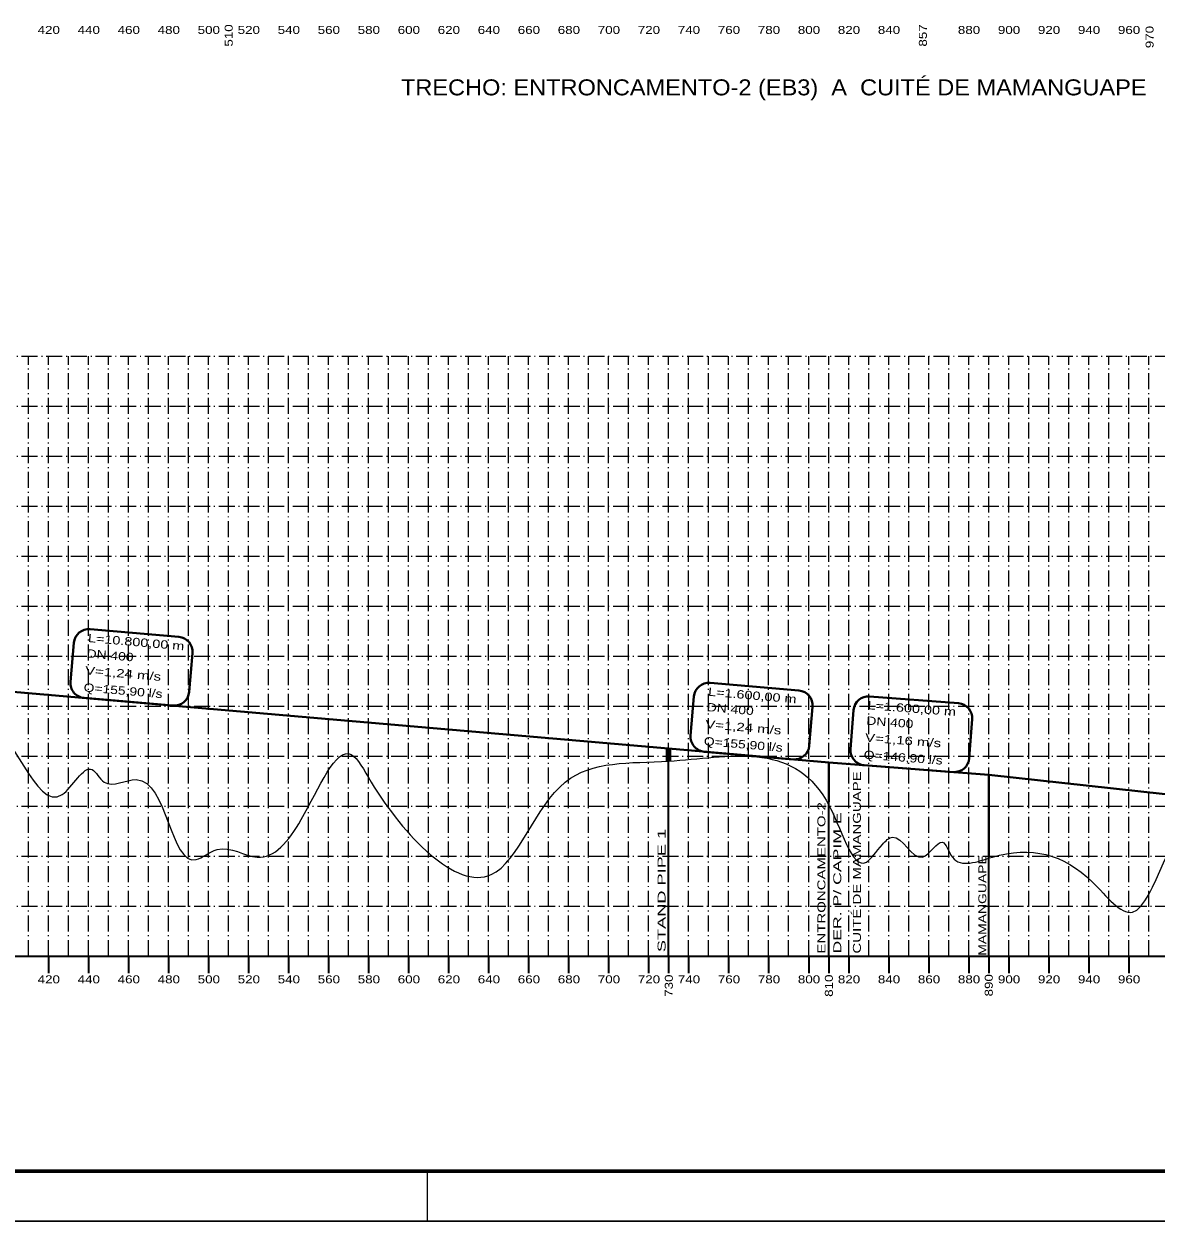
# Model space of a CAD drawing. Extents: x -4 to 42046, y -3 to 29697.
# Drawn here: x 11261 to 22579, y -3 to 11967 of the extents above; entities that cross this region are included whole.
import ezdxf
from ezdxf.enums import TextEntityAlignment as Align

# ---------------------------------------------------------------- set-up
doc = ezdxf.new("R2010")
doc.units = 0
doc.header["$LTSCALE"] = 32
doc.linetypes.add('DOT_DASHED', pattern=[7.7, 5, -1.2, 0.3, -1.2])
for name, color, linetype, lineweight in [('1', 7, 'DOT_DASHED', 13), ('24', 7, 'Continuous', 35), ('56', 7, 'Continuous', 13), ('62', 7, 'Continuous', 13), ('63', 7, 'Continuous', 25), ('7', 7, 'Continuous', 35), ('9', 7, 'Continuous', 40)]:
    doc.layers.add(name, color=color, linetype=linetype, lineweight=lineweight)

msp = doc.modelspace()

# ---------------------------------------------------------------- linework, layer by layer
at = {"layer": '1'}
for p, q in [((3105.77, 8646.17), (29145.77, 8646.17)), ((11305.77, 2646.17), (11305.77, 8646.17)), ((11505.77, 2646.17), (11505.77, 8646.17)), ((11705.77, 2646.17), (11705.77, 8646.17)), ((11905.77, 2646.17), (11905.77, 8646.17)), ((12105.77, 2646.17), (12105.77, 8646.17)), ((12305.77, 2646.17), (12305.77, 8646.17)), ((12505.77, 2646.17), (12505.77, 8646.17)), ((12705.77, 2646.17), (12705.77, 8646.17)), ((12905.77, 2646.17), (12905.77, 8646.17)), ((13105.77, 2646.17), (13105.77, 8646.17)), ((13305.77, 2646.17), (13305.77, 8646.17)), ((13505.77, 2646.17), (13505.77, 8646.17)), ((13705.77, 2646.17), (13705.77, 8646.17)), ((13905.77, 2646.17), (13905.77, 8646.17)), ((14105.77, 2646.17), (14105.77, 8646.17)), ((14305.77, 2646.17), (14305.77, 8646.17)), ((14505.77, 2646.17), (14505.77, 8646.17)), ((14705.77, 2646.17), (14705.77, 8646.17)), ((14905.77, 2646.17), (14905.77, 8646.17)), ((15105.77, 2646.17), (15105.77, 8646.17)), ((15305.77, 2646.17), (15305.77, 8646.17)), ((15505.77, 2646.17), (15505.77, 8646.17)), ((15705.77, 2646.17), (15705.77, 8646.17)), ((15905.77, 2646.17), (15905.77, 8646.17)), ((16105.77, 2646.17), (16105.77, 8646.17)), ((16305.77, 2646.17), (16305.77, 8646.17)), ((16505.77, 2646.17), (16505.77, 8646.17)), ((16705.77, 2646.17), (16705.77, 8646.17)), ((16905.77, 2646.17), (16905.77, 8646.17)), ((17105.77, 2646.17), (17105.77, 8646.17)), ((17305.77, 2646.17), (17305.77, 8646.17)), ((17505.77, 2646.17), (17505.77, 8646.17)), ((17705.77, 2646.17), (17705.77, 8646.17)), ((17905.77, 2646.17), (17905.77, 8646.17)), ((18105.77, 2646.17), (18105.77, 8646.17)), ((18305.77, 2646.17), (18305.77, 8646.17)), ((18505.77, 2646.17), (18505.77, 8646.17)), ((18705.77, 2646.17), (18705.77, 8646.17)), ((18905.77, 2646.17), (18905.77, 8646.17)), ((19105.77, 2646.17), (19105.77, 8646.17)), ((19305.77, 2646.17), (19305.77, 8646.17)), ((19505.77, 2646.17), (19505.77, 8646.17)), ((19705.77, 2646.17), (19705.77, 8646.17)), ((19905.77, 2646.17), (19905.77, 8646.17)), ((20105.77, 2646.17), (20105.77, 8646.17)), ((20305.77, 2646.17), (20305.77, 8646.17)), ((20505.77, 2646.17), (20505.77, 8646.17)), ((20705.77, 2646.17), (20705.77, 8646.17)), ((20905.77, 2646.17), (20905.77, 8646.17)), ((21105.77, 2646.17), (21105.77, 8646.17)), ((21305.77, 2646.17), (21305.77, 8646.17)), ((21505.77, 2646.17), (21505.77, 8646.17)), ((21705.77, 2646.17), (21705.77, 8646.17)), ((21905.77, 2646.17), (21905.77, 8646.17)), ((22105.77, 2646.17), (22105.77, 8646.17)), ((22305.77, 2646.17), (22305.77, 8646.17)), ((22505.77, 2646.17), (22505.77, 8646.17)), ((3105.77, 8146.17), (29145.77, 8146.17)), ((3105.77, 7646.17), (29145.77, 7646.17)), ((3105.77, 7146.17), (29145.77, 7146.17)), ((3105.77, 6646.17), (29145.77, 6646.17)), ((3105.77, 6146.17), (29145.77, 6146.17)), ((3105.77, 5646.17), (29145.77, 5646.17)), ((3105.77, 5146.17), (29145.77, 5146.17)), ((3105.77, 4646.17), (29145.77, 4646.17)), ((3105.77, 4146.17), (29145.77, 4146.17)), ((3105.77, 3646.17), (29145.77, 3646.17)), ((3105.77, 3146.17), (29145.77, 3146.17))]:
    msp.add_line(p, q, dxfattribs=at)
at = {"layer": '56'}
msp.add_spline([(3442.18, 3641.64), (3562.37, 3886.04), (3682.37, 4136.04), (3802.37, 4461.04), (3902.37, 4136.04), (3962.37, 3761.04), (4222.37, 4586.04), (4922.37, 4261.04), (5542.37, 4386.04), (5622.37, 4336.04), (5722.37, 4386.04), (5822.37, 4461.04), (6022.37, 4286.04), (6222.37, 4361.04), (6522.37, 4261.04), (6922.37, 4386.04), (7322.37, 4086.04), (7642.37, 4636.04), (7742.37, 4761.04), (8062.37, 4336.04), (8442.37, 4636.04), (8702.37, 4561.04), (9002.37, 4636.04), (9202.37, 4386.04), (9442.37, 4711.04), (9642.37, 4486.04), (9902.37, 4886.04), (10422.37, 4636.04), (10882.37, 4936.04), (11642.37, 4261.04), (11942.37, 4511.04), (12062.37, 4386.04), (12382.37, 4411.04), (12982.37, 3611.04), (13192.37, 3711.04), (13592.37, 3636.04), (14032.37, 4011.04), (14532.37, 4661.04), (14732.37, 4386.04), (15932.37, 3461.04), (16672.37, 4386.04), (17705.77, 4596.17), (19279.94, 4205.37), (19682.37, 3586.04), (19842.37, 3761.04), (19942.37, 3836.04), (20242.37, 3636.04), (20442.37, 3786.04), (20542.37, 3636.04), (20942.37, 3636.04), (21942.37, 3386.04), (22342.37, 3086.04), (22942.37, 3886.04), (23242.37, 3511.04), (23362.37, 3711.04), (23862.37, 3011.04), (24002.37, 3136.04), (24202.37, 3061.04), (24402.37, 3136.04), (24882.37, 2886.04), (25102.37, 2836.04), (25362.37, 3011.04), (26082.37, 2836.04), (26222.37, 2886.04), (26322.37, 2836.04), (26502.37, 2961.04), (26702.37, 2836.04), (27202.37, 3011.04), (27602.37, 2836.04), (27762.37, 2961.04), (27862.37, 2886.04), (27982.37, 2936.04), (28182.37, 2811.04), (28342.37, 2886.04), (28742.37, 2836.04), (29145.65, 2836.26)], degree=3, dxfattribs=at)
at = {"layer": '62', "lineweight": 35}
for p, q in [((19305.77, 2646.17), (19305.77, 4190.11)), ((20905.77, 2646.17), (20905.77, 3640.84)), ((3105.77, 2646.17), (29145.77, 2646.17)), ((11505.77, 2646.17), (11505.77, 2475.48)), ((11905.77, 2646.17), (11905.77, 2475.48)), ((12305.77, 2646.17), (12305.77, 2475.48)), ((12705.77, 2646.17), (12705.77, 2475.48)), ((13105.77, 2646.17), (13105.77, 2475.48)), ((13505.77, 2646.17), (13505.77, 2475.48)), ((13905.77, 2646.17), (13905.77, 2475.48)), ((14305.77, 2646.17), (14305.77, 2475.48)), ((14705.77, 2646.17), (14705.77, 2475.48)), ((15105.77, 2646.17), (15105.77, 2475.48)), ((15505.77, 2646.17), (15505.77, 2475.48)), ((15905.77, 2646.17), (15905.77, 2475.48)), ((16305.77, 2646.17), (16305.77, 2475.48)), ((16705.77, 2646.17), (16705.77, 2475.48)), ((17105.77, 2646.17), (17105.77, 2475.48)), ((17505.77, 2646.17), (17505.77, 2475.48)), ((17705.77, 2646.17), (17705.77, 2475.48)), ((17905.77, 2646.17), (17905.77, 2475.48)), ((18305.77, 2646.17), (18305.77, 2475.48)), ((18705.77, 2646.17), (18705.77, 2475.48)), ((19105.77, 2646.17), (19105.77, 2475.48)), ((19305.77, 2646.17), (19305.77, 2475.48)), ((19505.77, 2646.17), (19505.77, 2475.48)), ((19905.77, 2646.17), (19905.77, 2475.48)), ((20305.77, 2646.17), (20305.77, 2475.48)), ((20705.77, 2646.17), (20705.77, 2475.48)), ((20905.77, 2646.17), (20905.77, 2475.48)), ((21105.77, 2646.17), (21105.77, 2475.48)), ((21505.77, 2646.17), (21505.77, 2475.48)), ((21905.77, 2646.17), (21905.77, 2475.48)), ((22305.77, 2646.17), (22305.77, 2475.48))]:
    msp.add_line(p, q, dxfattribs=at)
at = {"layer": '63', "lineweight": 60}
msp.add_line((41545.8, 497.03), (1245.8, 497.03), dxfattribs=at)
at = {"layer": '63'}
msp.add_line((15295.8, -2.97), (15295.8, 497.03), dxfattribs=at)
for points in [[(-4.21, -2.97), (42045.8, -2.97), (42045.8, 29697.03)], [(-4.21, -2.97), (42045.8, -2.97), (-4.21, -2.97)]]:
    msp.add_lwpolyline(points, dxfattribs=at)
at = {"layer": '63', "lineweight": 60}
msp.add_lwpolyline([(23554.57, 497.03), (1245.8, 497.03), (1245.8, 29197.03)], dxfattribs=at)
at = {"layer": '7'}
for p, q in [((17688.43, 4596.4), (17688.43, 4715.71)), ((17705.77, 2646.17), (17705.77, 4721.17))]:
    msp.add_line(p, q, dxfattribs=at)
msp.add_lwpolyline([(17723.11, 4595.79), (17723.11, 4715.71), (17688.43, 4715.71)], dxfattribs=at)
at = {"layer": '9'}
for p, q in [((11921.57, 5915), (12809.1, 5838.13)), ((11759.19, 5778.5), (11725.51, 5389.7)), ((12945.59, 5675.74), (12911.92, 5286.94)), ((18121.57, 5378), (19009.1, 5301.13)), ((11862.01, 5227.31), (12749.54, 5150.44)), ((17959.19, 5241.5), (17925.51, 4852.7)), ((19714.79, 5243.33), (20603, 5174.77)), ((19145.59, 5138.74), (19111.92, 4749.94)), ((19553.69, 5105.32), (19523.66, 4716.21)), ((20741.01, 5013.67), (20710.97, 4624.57)), ((18062.01, 4690.31), (18949.54, 4613.44)), ((19305.77, 4190.11), (19305.77, 4582.59)), ((19661.67, 4555.11), (20549.88, 4486.56)), ((20905.77, 3640.84), (20905.77, 4459.09))]:
    msp.add_line(p, q, dxfattribs=at)
msp.add_lwpolyline([(3105.77, 6140.34), (4205.77, 5946.84), (6905.77, 5656.59), (17705.77, 4721.17), (19305.77, 4582.59), (20905.77, 4459.09), (29145.77, 3554.09)], dxfattribs=at)
for centre, start, end in [((11908.63, 5765.56), 85.0498, 175.0498), ((12796.15, 5688.69), 355.0498, 85.0498), ((11874.95, 5376.75), 175.0498, 265.0498), ((12762.48, 5299.88), 265.0498, 355.0498), ((18108.63, 5228.56), 85.0498, 175.0498), ((18996.15, 5151.69), 355.0498, 85.0498), ((19703.24, 5093.77), 85.58623, 175.58623), ((20591.45, 5025.22), 355.58623, 85.58623), ((18074.95, 4839.75), 175.0498, 265.0498), ((18962.48, 4762.88), 265.0498, 355.0498), ((19673.21, 4704.67), 175.58623, 265.58623), ((20561.42, 4636.11), 265.58623, 355.58623)]:
    msp.add_arc(centre, 150, start, end, dxfattribs=at)

# ---------------------------------------------------------------- texts
at = {"layer": '24'}
for s, height, width, p in [('420', 80, 1.25, (11508.9, 11866.51)), ('440', 80, 1.25, (11908.9, 11866.51)), ('460', 80, 1.25, (12308.9, 11866.51)), ('480', 80, 1.25, (12708.9, 11866.51)), ('500', 80, 1.25, (13108.9, 11866.51)), ('520', 80, 1.25, (13508.9, 11866.51)), ('540', 80, 1.25, (13908.9, 11866.51)), ('560', 80, 1.25, (14308.9, 11866.51)), ('580', 80, 1.25, (14708.9, 11866.51)), ('600', 80, 1.25, (15108.9, 11866.51)), ('620', 80, 1.25, (15508.9, 11866.51)), ('640', 80, 1.25, (15908.9, 11866.51)), ('660', 80, 1.25, (16308.9, 11866.51)), ('680', 80, 1.25, (16708.9, 11866.51)), ('700', 80, 1.25, (17108.9, 11866.51)), ('720', 80, 1.25, (17508.9, 11866.51)), ('740', 80, 1.25, (17908.9, 11866.51)), ('760', 80, 1.25, (18308.9, 11866.51)), ('780', 80, 1.25, (18708.9, 11866.51)), ('800', 80, 1.25, (19108.9, 11866.51)), ('820', 80, 1.25, (19508.9, 11866.51)), ('840', 80, 1.25, (19908.9, 11866.51)), ('880', 80, 1.25, (20708.9, 11866.51)), ('900', 80, 1.25, (21108.9, 11866.51)), ('920', 80, 1.25, (21508.9, 11866.51)), ('940', 80, 1.25, (21908.9, 11866.51)), ('960', 80, 1.25, (22308.9, 11866.51)), ('TRECHO: ENTRONCAMENTO-2 (EB3)  A  CUITÉ DE MAMANGUAPE', 160, 1.1, (18756.79, 11252.52)), ('420', 80, 1.25, (11509.27, 2373.89)), ('440', 80, 1.25, (11909.27, 2373.89)), ('460', 80, 1.25, (12309.27, 2373.89)), ('480', 80, 1.25, (12709.27, 2373.89)), ('500', 80, 1.25, (13109.27, 2373.89)), ('520', 80, 1.25, (13509.27, 2373.89)), ('540', 80, 1.25, (13909.27, 2373.89)), ('560', 80, 1.25, (14309.27, 2373.89)), ('580', 80, 1.25, (14709.27, 2373.89)), ('600', 80, 1.25, (15109.27, 2373.89)), ('620', 80, 1.25, (15509.27, 2373.89)), ('640', 80, 1.25, (15909.27, 2373.89)), ('660', 80, 1.25, (16309.27, 2373.89)), ('680', 80, 1.25, (16709.27, 2373.89)), ('700', 80, 1.25, (17109.27, 2373.89)), ('720', 80, 1.25, (17509.27, 2373.89)), ('740', 80, 1.25, (17909.27, 2373.89)), ('760', 80, 1.25, (18309.27, 2373.89)), ('780', 80, 1.25, (18709.27, 2373.89)), ('800', 80, 1.25, (19109.27, 2373.89)), ('820', 80, 1.25, (19509.27, 2373.89)), ('840', 80, 1.25, (19909.27, 2373.89)), ('860', 80, 1.25, (20309.27, 2373.89)), ('880', 80, 1.25, (20709.27, 2373.89)), ('900', 80, 1.25, (21109.27, 2373.89)), ('920', 80, 1.25, (21509.27, 2373.89)), ('940', 80, 1.25, (21909.27, 2373.89)), ('960', 80, 1.25, (22309.27, 2373.89))]:
    msp.add_text(s, height=height, dxfattribs=dict(at, width=width)).set_placement(p, align=Align.CENTER)
at = {"layer": '24', "width": 1.25}
for s, p in [('510', (13347.48, 11851.45)), ('857', (20287.48, 11851.45)), ('970', (22554.16, 11835.44)), ('730', (17747.53, 2350.51)), ('810', (19347.53, 2350.51)), ('890', (20946.18, 2354.43))]:
    msp.add_text(s, height=80, rotation=90, dxfattribs=at).set_placement(p, align=Align.CENTER)
at = {"layer": '24'}
for s, width, p in [('CUITÉ DE MAMANGUAPE', 1.4, (19628.11, 2671.53)), ('ENTRONCAMENTO-2', 1.4, (19273.17, 2671.53)), ('DER. P/ CAPIM E', 1.65, (19431.87, 2671.53)), ('STAND PIPE 1', 1.7, (17675.45, 2685.5)), ('MAMANGUAPE', 1.3, (20882.33, 2649.88))]:
    msp.add_text(s, height=80, rotation=90, dxfattribs=dict(at, width=width)).set_placement(p)
at = {"layer": '9'}
for s, rotation, width, p in [('L=10.800,00 m', 355.05, 1.3, (11897.57, 5787.13)), ('DN 400', 355.05, 1.25, (11884.23, 5633.21)), ('V=1,24 m/s', 355.05, 1.35, (11869.51, 5463.26)), ('Q=155,90 l/s', 355.05, 1.25, (11854.79, 5293.3)), ('L=1.600,00 m', 355.05, 1.3, (18097.57, 5250.13)), ('DN 400', 355.05, 1.25, (18084.23, 5096.21)), ('L=1.600,00 m', 355.586, 1.3, (19691.98, 5115.24)), ('DN 400', 355.586, 1.25, (19680.09, 4961.2)), ('V=1,24 m/s', 355.05, 1.35, (18069.51, 4926.26)), ('Q=155,90 l/s', 355.05, 1.25, (18054.79, 4756.3)), ('V=1,16 m/s', 355.586, 1.35, (19666.96, 4791.12)), ('Q=146,90 l/s', 355.586, 1.25, (19653.84, 4621.04))]:
    msp.add_text(s, height=82.98, rotation=rotation, dxfattribs=dict(at, width=width)).set_placement(p)

doc.saveas('drawing.dxf')
